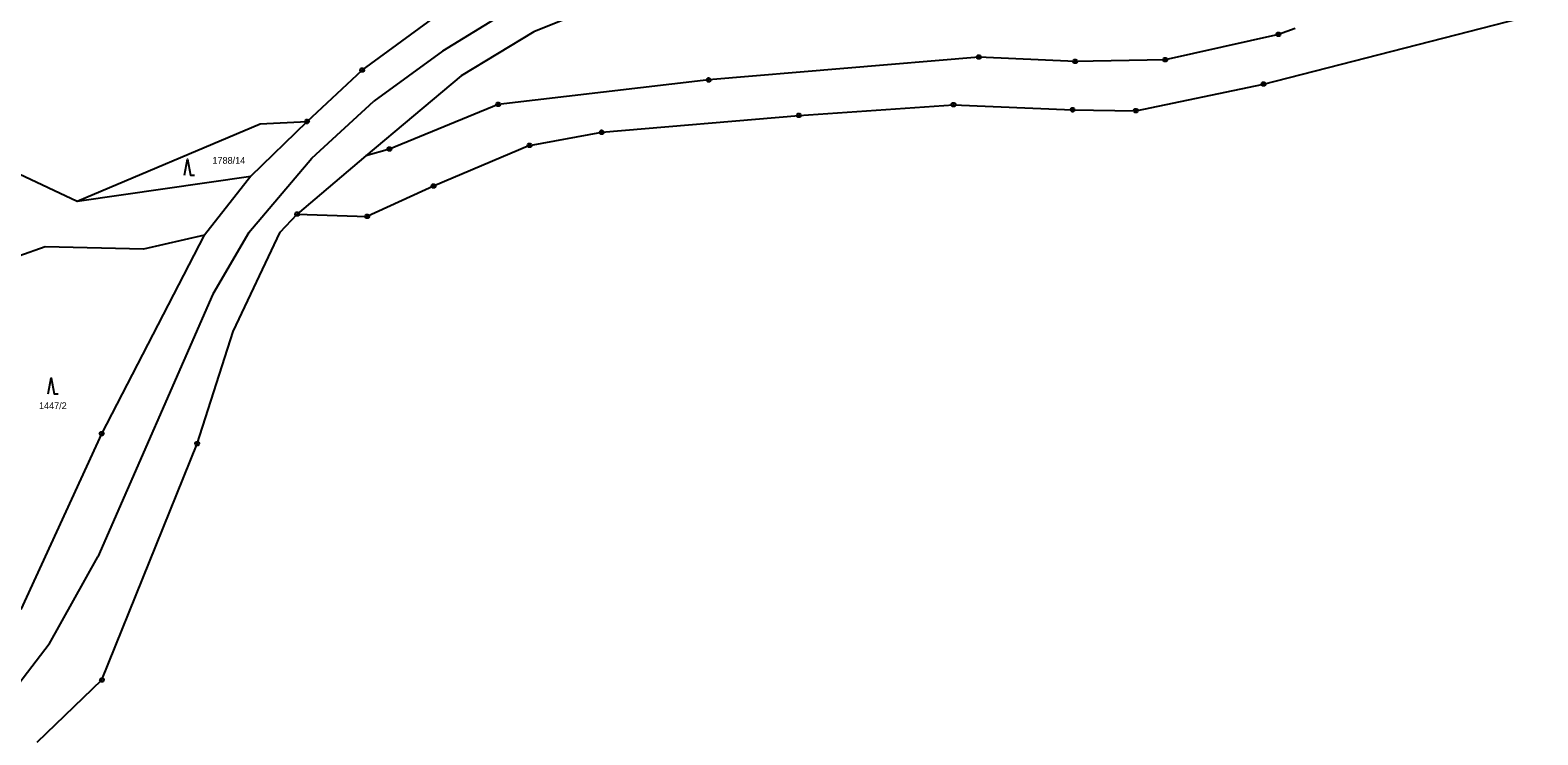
# Model space of a CAD drawing. Extents: x -779618 to -776429, y -1144546 to -1143350.
# Drawn here: x -779255.7 to -778878.5, y -1144283.6 to -1144107.3 of the extents above; entities that cross this region are included whole.
import ezdxf

# ---------------------------------------------------------------- set-up
doc = ezdxf.new("R2010")
doc.units = 0
for name, color, linetype in [('1', 7, 'Continuous'), ('2', 7, 'Continuous'), ('3', 7, 'Continuous'), ('6', 7, 'Continuous'), ('8', 7, 'Continuous')]:
    doc.layers.add(name, color=color, linetype=linetype)

msp = doc.modelspace()

# ---------------------------------------------------------------- linework, layer by layer
at = {"layer": '1'}
for p, q in [((-779098.86, -1144095.32), (-779129.69, -1144107.76)), ((-779172.68, -1144117.31), (-779154.06, -1144103.74)), ((-778947.15, -1144120.83), (-778870.04, -1144101.07)), ((-779129.69, -1144107.76), (-779147.92, -1144118.78)), ((-778943.37, -1144108.37), (-778971.75, -1144114.74)), ((-778939.23, -1144106.88), (-778943.37, -1144108.37)), ((-779018.36, -1144114.07), (-779085.95, -1144119.77)), ((-778994.28, -1144115.14), (-779018.36, -1144114.07)), ((-778971.75, -1144114.74), (-778994.28, -1144115.14)), ((-779186.45, -1144130.18), (-779172.68, -1144117.31)), ((-779147.92, -1144118.78), (-779171.74, -1144138.75)), ((-779085.95, -1144119.77), (-779138.61, -1144125.92)), ((-778979.09, -1144127.47), (-778947.15, -1144120.83)), ((-779138.61, -1144125.92), (-779165.83, -1144137.06)), ((-779063.38, -1144128.65), (-779024.7, -1144125.97)), ((-779024.7, -1144125.97), (-778994.89, -1144127.26)), ((-778994.89, -1144127.26), (-778979.09, -1144127.47)), ((-779243.97, -1144150.07), (-779198.19, -1144130.72)), ((-779200.53, -1144143.85), (-779186.45, -1144130.18)), ((-779198.19, -1144130.72), (-779186.45, -1144130.18)), ((-779112.73, -1144132.86), (-779063.38, -1144128.65)), ((-779130.77, -1144136.18), (-779112.73, -1144132.86)), ((-779165.83, -1144137.06), (-779171.74, -1144138.75)), ((-779130.77, -1144136.18), (-779154.78, -1144146.35)), ((-779171.74, -1144138.75), (-779188.9, -1144153.34)), ((-779258.5, -1144143.27), (-779243.97, -1144150.07)), ((-779243.97, -1144150.07), (-779200.53, -1144143.85)), ((-779200.53, -1144143.85), (-779212.15, -1144158.64)), ((-779154.78, -1144146.35), (-779171.4, -1144153.94)), ((-779193.18, -1144157.9), (-779188.9, -1144153.34)), ((-779188.9, -1144153.34), (-779171.4, -1144153.94)), ((-779237.84, -1144208.3), (-779212.15, -1144158.64)), ((-779212.15, -1144158.64), (-779227.37, -1144162.15)), ((-779204.91, -1144182.69), (-779193.18, -1144157.9)), ((-779251.94, -1144161.56), (-779258.57, -1144163.89)), ((-779227.37, -1144162.15), (-779251.94, -1144161.56)), ((-779213.93, -1144210.8), (-779204.91, -1144182.69)), ((-779258.02, -1144252.3), (-779237.84, -1144208.3)), ((-779237.76, -1144269.92), (-779213.93, -1144210.8)), ((-779253.95, -1144285.5), (-779237.76, -1144269.92))]:
    msp.add_line(p, q, dxfattribs=at)
at = {"layer": '3'}
for points in [[(-779217.11, -1144143.58), (-779216.36, -1144139.58), (-779215.61, -1144143.58), (-779214.61, -1144143.58)], [(-779251.22, -1144198.35), (-779250.47, -1144194.35), (-779249.72, -1144198.35), (-779248.72, -1144198.35)]]:
    msp.add_lwpolyline(points, dxfattribs=at)
at = {"layer": '6'}
for p, q in [((-779131.84, -1144099.9), (-779152.54, -1144112.6)), ((-779152.54, -1144112.6), (-779169.73, -1144125.09)), ((-779185.28, -1144139.38), (-779169.73, -1144125.09)), ((-779201.01, -1144157.94), (-779185.28, -1144139.38)), ((-779201.01, -1144157.94), (-779210.03, -1144173.37)), ((-779210.03, -1144173.37), (-779238.76, -1144239.1)), ((-779250.95, -1144260.96), (-779238.76, -1144239.1)), ((-779250.95, -1144260.96), (-779265.64, -1144280.11))]:
    msp.add_line(p, q, dxfattribs=at)
at = {"layer": '8'}
for p, q in [((-778943.49, -1144108.37), (-778943.25, -1144108.37)), ((-779018.48, -1144114.07), (-779018.24, -1144114.07)), ((-778994.4, -1144115.14), (-778994.16, -1144115.14)), ((-778971.87, -1144114.74), (-778971.63, -1144114.74)), ((-779172.8, -1144117.31), (-779172.56, -1144117.31)), ((-779086.07, -1144119.77), (-779085.83, -1144119.77)), ((-778947.27, -1144120.83), (-778947.03, -1144120.83)), ((-779138.73, -1144125.92), (-779138.49, -1144125.92)), ((-779024.82, -1144125.97), (-779024.58, -1144125.97)), ((-778995.01, -1144127.26), (-778994.77, -1144127.26)), ((-779186.57, -1144130.18), (-779186.33, -1144130.18)), ((-779063.5, -1144128.65), (-779063.26, -1144128.65)), ((-778979.21, -1144127.47), (-778978.97, -1144127.47)), ((-779112.85, -1144132.86), (-779112.61, -1144132.86)), ((-779165.95, -1144137.06), (-779165.71, -1144137.06)), ((-779130.89, -1144136.18), (-779130.65, -1144136.18)), ((-779154.9, -1144146.35), (-779154.66, -1144146.35)), ((-779189.02, -1144153.34), (-779188.78, -1144153.34)), ((-779171.52, -1144153.94), (-779171.28, -1144153.94)), ((-779237.96, -1144208.3), (-779237.72, -1144208.3)), ((-779214.05, -1144210.8), (-779213.81, -1144210.8)), ((-779237.88, -1144269.92), (-779237.64, -1144269.92))]:
    msp.add_line(p, q, dxfattribs=at)
for points in [[(-778943.22, -1144107.89), (-778942.97, -1144108.07), (-778942.87, -1144108.36), (-778942.97, -1144108.65), (-778943.22, -1144108.83), (-778943.53, -1144108.83), (-778943.78, -1144108.65), (-778943.88, -1144108.36), (-778943.78, -1144108.07), (-778943.53, -1144107.89)], [(-779018.21, -1144113.59), (-779017.96, -1144113.77), (-779017.86, -1144114.06), (-779017.96, -1144114.35), (-779018.21, -1144114.53), (-779018.52, -1144114.53), (-779018.77, -1144114.35), (-779018.87, -1144114.06), (-779018.77, -1144113.77), (-779018.52, -1144113.59)], [(-778994.13, -1144114.66), (-778993.88, -1144114.84), (-778993.78, -1144115.13), (-778993.88, -1144115.42), (-778994.13, -1144115.6), (-778994.44, -1144115.6), (-778994.69, -1144115.42), (-778994.79, -1144115.13), (-778994.69, -1144114.84), (-778994.44, -1144114.66)], [(-778971.6, -1144114.26), (-778971.35, -1144114.44), (-778971.25, -1144114.73), (-778971.35, -1144115.02), (-778971.6, -1144115.2), (-778971.91, -1144115.2), (-778972.16, -1144115.02), (-778972.26, -1144114.73), (-778972.16, -1144114.44), (-778971.91, -1144114.26)], [(-779172.53, -1144116.83), (-779172.28, -1144117.01), (-779172.18, -1144117.3), (-779172.28, -1144117.59), (-779172.53, -1144117.77), (-779172.84, -1144117.77), (-779173.09, -1144117.59), (-779173.19, -1144117.3), (-779173.09, -1144117.01), (-779172.84, -1144116.83)], [(-779085.8, -1144119.29), (-779085.55, -1144119.47), (-779085.45, -1144119.76), (-779085.55, -1144120.05), (-779085.8, -1144120.23), (-779086.11, -1144120.23), (-779086.36, -1144120.05), (-779086.46, -1144119.76), (-779086.36, -1144119.47), (-779086.11, -1144119.29)], [(-778947, -1144120.35), (-778946.75, -1144120.53), (-778946.65, -1144120.82), (-778946.75, -1144121.11), (-778947, -1144121.29), (-778947.31, -1144121.29), (-778947.56, -1144121.11), (-778947.66, -1144120.82), (-778947.56, -1144120.53), (-778947.31, -1144120.35)], [(-779138.46, -1144125.44), (-779138.21, -1144125.62), (-779138.11, -1144125.91), (-779138.21, -1144126.2), (-779138.46, -1144126.38), (-779138.77, -1144126.38), (-779139.02, -1144126.2), (-779139.12, -1144125.91), (-779139.02, -1144125.62), (-779138.77, -1144125.44)], [(-779024.55, -1144125.49), (-779024.3, -1144125.67), (-779024.2, -1144125.96), (-779024.3, -1144126.25), (-779024.55, -1144126.43), (-779024.86, -1144126.43), (-779025.11, -1144126.25), (-779025.21, -1144125.96), (-779025.11, -1144125.67), (-779024.86, -1144125.49)], [(-778994.74, -1144126.78), (-778994.49, -1144126.96), (-778994.39, -1144127.25), (-778994.49, -1144127.54), (-778994.74, -1144127.72), (-778995.05, -1144127.72), (-778995.3, -1144127.54), (-778995.4, -1144127.25), (-778995.3, -1144126.96), (-778995.05, -1144126.78)], [(-778978.94, -1144126.99), (-778978.69, -1144127.17), (-778978.59, -1144127.46), (-778978.69, -1144127.75), (-778978.94, -1144127.93), (-778979.25, -1144127.93), (-778979.5, -1144127.75), (-778979.6, -1144127.46), (-778979.5, -1144127.17), (-778979.25, -1144126.99)], [(-779186.3, -1144129.7), (-779186.05, -1144129.88), (-779185.95, -1144130.17), (-779186.05, -1144130.46), (-779186.3, -1144130.64), (-779186.61, -1144130.64), (-779186.86, -1144130.46), (-779186.96, -1144130.17), (-779186.86, -1144129.88), (-779186.61, -1144129.7)], [(-779063.23, -1144128.17), (-779062.98, -1144128.35), (-779062.88, -1144128.64), (-779062.98, -1144128.93), (-779063.23, -1144129.11), (-779063.54, -1144129.11), (-779063.79, -1144128.93), (-779063.89, -1144128.64), (-779063.79, -1144128.35), (-779063.54, -1144128.17)], [(-779112.58, -1144132.38), (-779112.33, -1144132.56), (-779112.23, -1144132.85), (-779112.33, -1144133.14), (-779112.58, -1144133.32), (-779112.89, -1144133.32), (-779113.14, -1144133.14), (-779113.24, -1144132.85), (-779113.14, -1144132.56), (-779112.89, -1144132.38)], [(-779165.68, -1144136.58), (-779165.43, -1144136.76), (-779165.33, -1144137.05), (-779165.43, -1144137.34), (-779165.68, -1144137.52), (-779165.99, -1144137.52), (-779166.24, -1144137.34), (-779166.34, -1144137.05), (-779166.24, -1144136.76), (-779165.99, -1144136.58)], [(-779130.62, -1144135.7), (-779130.37, -1144135.88), (-779130.27, -1144136.17), (-779130.37, -1144136.46), (-779130.62, -1144136.64), (-779130.93, -1144136.64), (-779131.18, -1144136.46), (-779131.28, -1144136.17), (-779131.18, -1144135.88), (-779130.93, -1144135.7)], [(-779154.63, -1144145.87), (-779154.38, -1144146.05), (-779154.28, -1144146.34), (-779154.38, -1144146.63), (-779154.63, -1144146.81), (-779154.94, -1144146.81), (-779155.19, -1144146.63), (-779155.29, -1144146.34), (-779155.19, -1144146.05), (-779154.94, -1144145.87)], [(-779188.75, -1144152.86), (-779188.5, -1144153.04), (-779188.4, -1144153.33), (-779188.5, -1144153.62), (-779188.75, -1144153.8), (-779189.06, -1144153.8), (-779189.31, -1144153.62), (-779189.41, -1144153.33), (-779189.31, -1144153.04), (-779189.06, -1144152.86)], [(-779171.25, -1144153.46), (-779171, -1144153.64), (-779170.9, -1144153.93), (-779171, -1144154.22), (-779171.25, -1144154.4), (-779171.56, -1144154.4), (-779171.81, -1144154.22), (-779171.91, -1144153.93), (-779171.81, -1144153.64), (-779171.56, -1144153.46)], [(-779237.69, -1144207.82), (-779237.44, -1144208), (-779237.34, -1144208.29), (-779237.44, -1144208.58), (-779237.69, -1144208.76), (-779238, -1144208.76), (-779238.25, -1144208.58), (-779238.35, -1144208.29), (-779238.25, -1144208), (-779238, -1144207.82)], [(-779213.78, -1144210.32), (-779213.53, -1144210.5), (-779213.43, -1144210.79), (-779213.53, -1144211.08), (-779213.78, -1144211.26), (-779214.09, -1144211.26), (-779214.34, -1144211.08), (-779214.44, -1144210.79), (-779214.34, -1144210.5), (-779214.09, -1144210.32)], [(-779237.61, -1144269.44), (-779237.36, -1144269.62), (-779237.26, -1144269.91), (-779237.36, -1144270.2), (-779237.61, -1144270.38), (-779237.92, -1144270.38), (-779238.17, -1144270.2), (-779238.27, -1144269.91), (-779238.17, -1144269.62), (-779237.92, -1144269.44)]]:
    msp.add_lwpolyline(points, close=True, dxfattribs=at)

# ---------------------------------------------------------------- texts
at = {"layer": '2'}
for s, p in [('1788/14', (-779210.13, -1144140.76)), ('1447/2', (-779253.53, -1144202.14))]:
    msp.add_text(s, height=1.7, dxfattribs=at).set_placement(p)

doc.saveas('drawing.dxf')
